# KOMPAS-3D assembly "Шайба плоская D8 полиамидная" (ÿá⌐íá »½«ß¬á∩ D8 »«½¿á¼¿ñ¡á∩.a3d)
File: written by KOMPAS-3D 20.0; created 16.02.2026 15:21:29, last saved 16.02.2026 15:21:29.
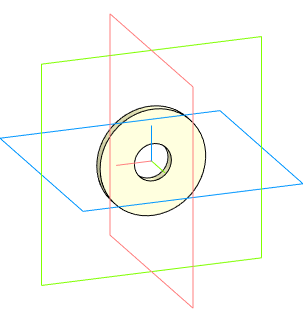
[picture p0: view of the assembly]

Document properties: Автор: admin; Полное имя файла: P:\INSTART\Технический отдел\ОР\Прочие задачи\КД на номенклатурный ряд\КД на типоразмеры дросселей\Сетевые дроссели ISF\ISF-4\Тип 1\ISF-132_256-4\0723\Новая папка\Шайба плоская D8 полиамидная.a3d

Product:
- Part/product: Шайба плоская D8 полиамидная
  - Component [detail]: Шайба ГОСТ Р ИСО 10673 - L - 8 - 25CrMo4  | source file: Шайба ГОСТ Р ИСО 10673 - L - 8 - 25CrMo4.m3d

Referenced files in P:\INSTART\Технический отдел\ОР\Прочие задачи\КД на номенклатурный ряд\КД на типоразмеры дросселей\Сетевые дроссели ISF\ISF-4\Тип 1\ISF-132_256-4\0723\Новая папка\: Шайба ГОСТ Р ИСО 10673 - L - 8 - 25CrMo4.m3d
